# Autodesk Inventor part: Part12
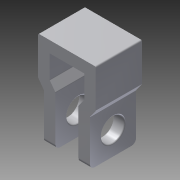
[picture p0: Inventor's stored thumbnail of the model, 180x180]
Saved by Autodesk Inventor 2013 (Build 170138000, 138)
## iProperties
Created: 2009-11
Part Number: Part12
Document SubType Name: Modeling
Designer: pokornp
Density: 1 g/cm^3
Material: Generic
Author: pokornp
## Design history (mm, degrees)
sketch "Sketch3"
  geometry: L1 (-75, 0)-(0, 0); L2 (0, 0)-(0, 50); L3 (0, 50)-(-125, 50); L4 (-125, 50)-(-125, -116.281); L5 (-125, -116.281)-(-100, -150.599); L6 (-100, -150.599)-(-100, -350); L7 (-100, -350)-(-50, -350); L8 (-50, -350)-(-50, -134.319); L9 (-50, -134.319)-(-75, -100); L10 (-75, -100)-(-75, 0); L11 (50, -350)-(50, -134.319); L12 (100, -350)-(50, -350); L13 (100, -150.599)-(100, -350); L14 (125, -116.281)-(100, -150.599); L15 (50, -134.319)-(75, -100); L16 (75, -100)-(75, 0); L17 (125, 50)-(125, -116.281); L18 (0, 50)-(125, 50); L19 (75, 0)-(0, 0); 1 further point
  constraints: 38 end point, 8 symmetric about line, 7 parallel, 1 coincident, 1 horizontal, 1 perpendicular
  dimensions: "t" = 50 distance between parallel lines of L3 L1; "d1" = 50 distance between parallel lines of L4 L10 (= t); "d2" = 50 distance between parallel lines of L5 L9 (= t); "d3" = 50 distance between parallel lines of L8 L6 (= t); "d4" = 75 distance between parallel lines of L2 L10; "d5" = 50 distance between parallel lines of L8 L2; "d8" = 100 distance of L16.end L15.end; "d9" = 400 distance between parallel lines of L12 L18
extrude "Extrusion1" new body sketch "Sketch3" distance "d6" = 200; taper "d7" = 0 deg
hole "Hole1" diameter "d12" = 100; stored, may be unused: countersink angle "d16" = 90 deg, drill point angle "d18" = 118 deg; dims "d10" = 100, "d11" = 100, "d13" = 6, "d14" = 4, "d15" = 2, "d17" = 8
fillet "Fillet1" dims "d19" = 20
fillet "Fillet2" dims "d20" = 5
fillet "Fillet3" dims "d21" = 5
body "Solid1"
